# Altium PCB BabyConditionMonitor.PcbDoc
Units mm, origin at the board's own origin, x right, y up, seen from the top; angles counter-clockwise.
Board outline 40.15 x 20.15 mm, 2 copper layers (Top Layer, Bottom Layer), stack 0.791 mm thick; 52 components, 44 nets, 238 pads, 64 vias.
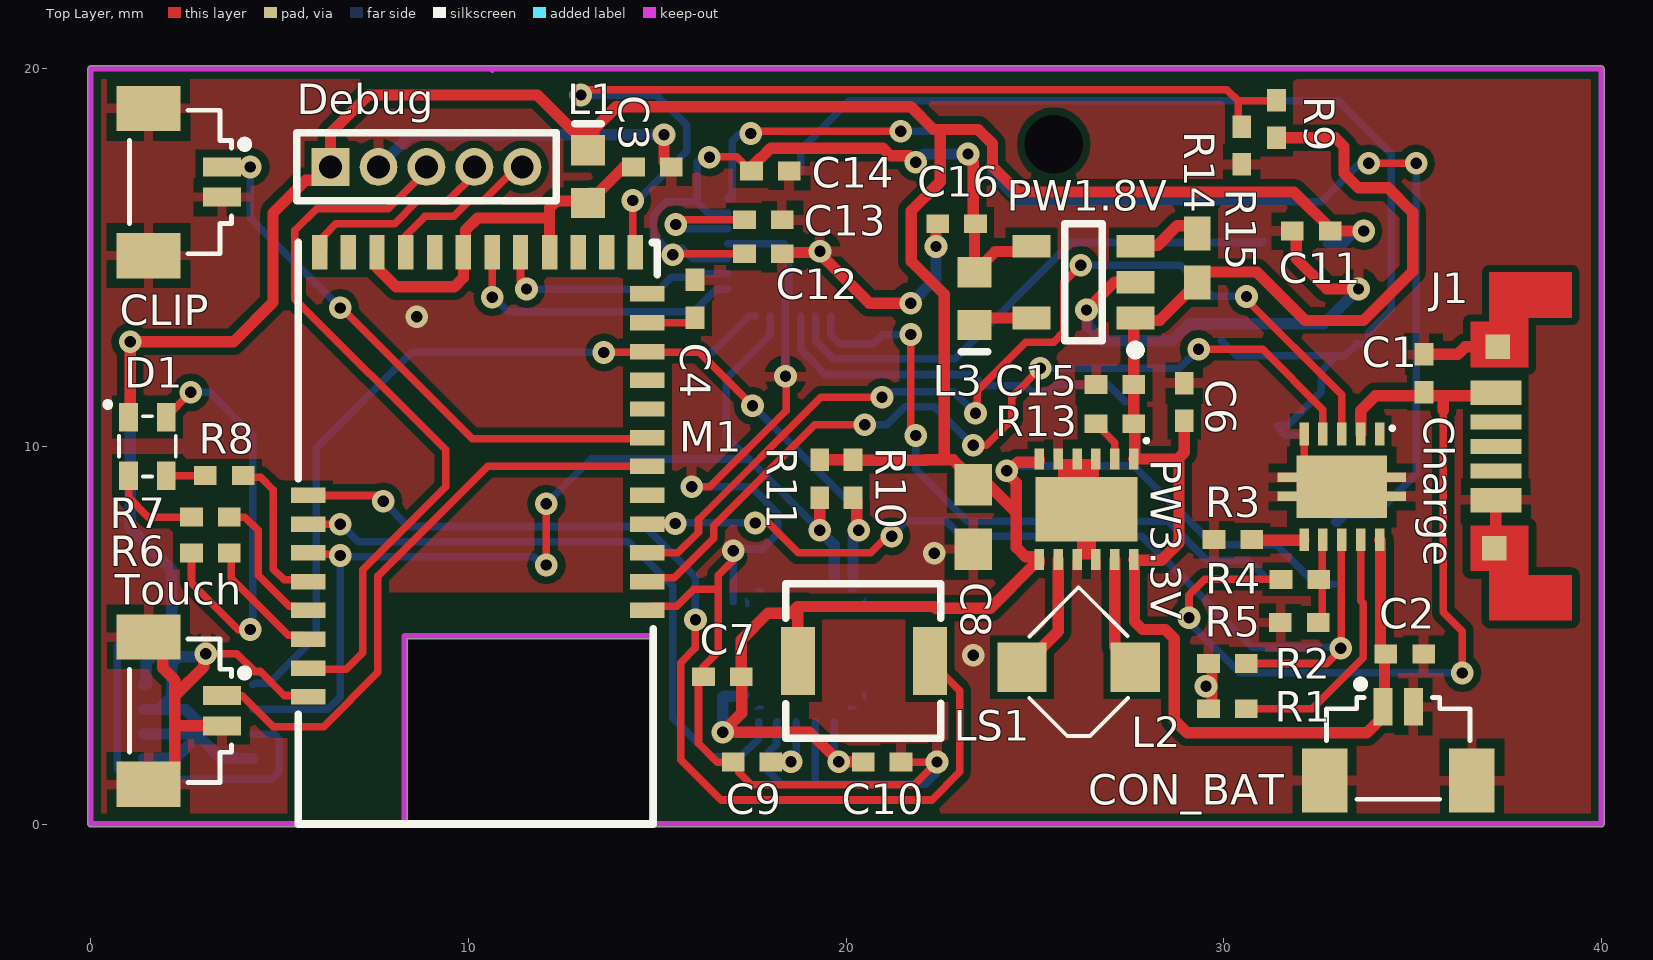
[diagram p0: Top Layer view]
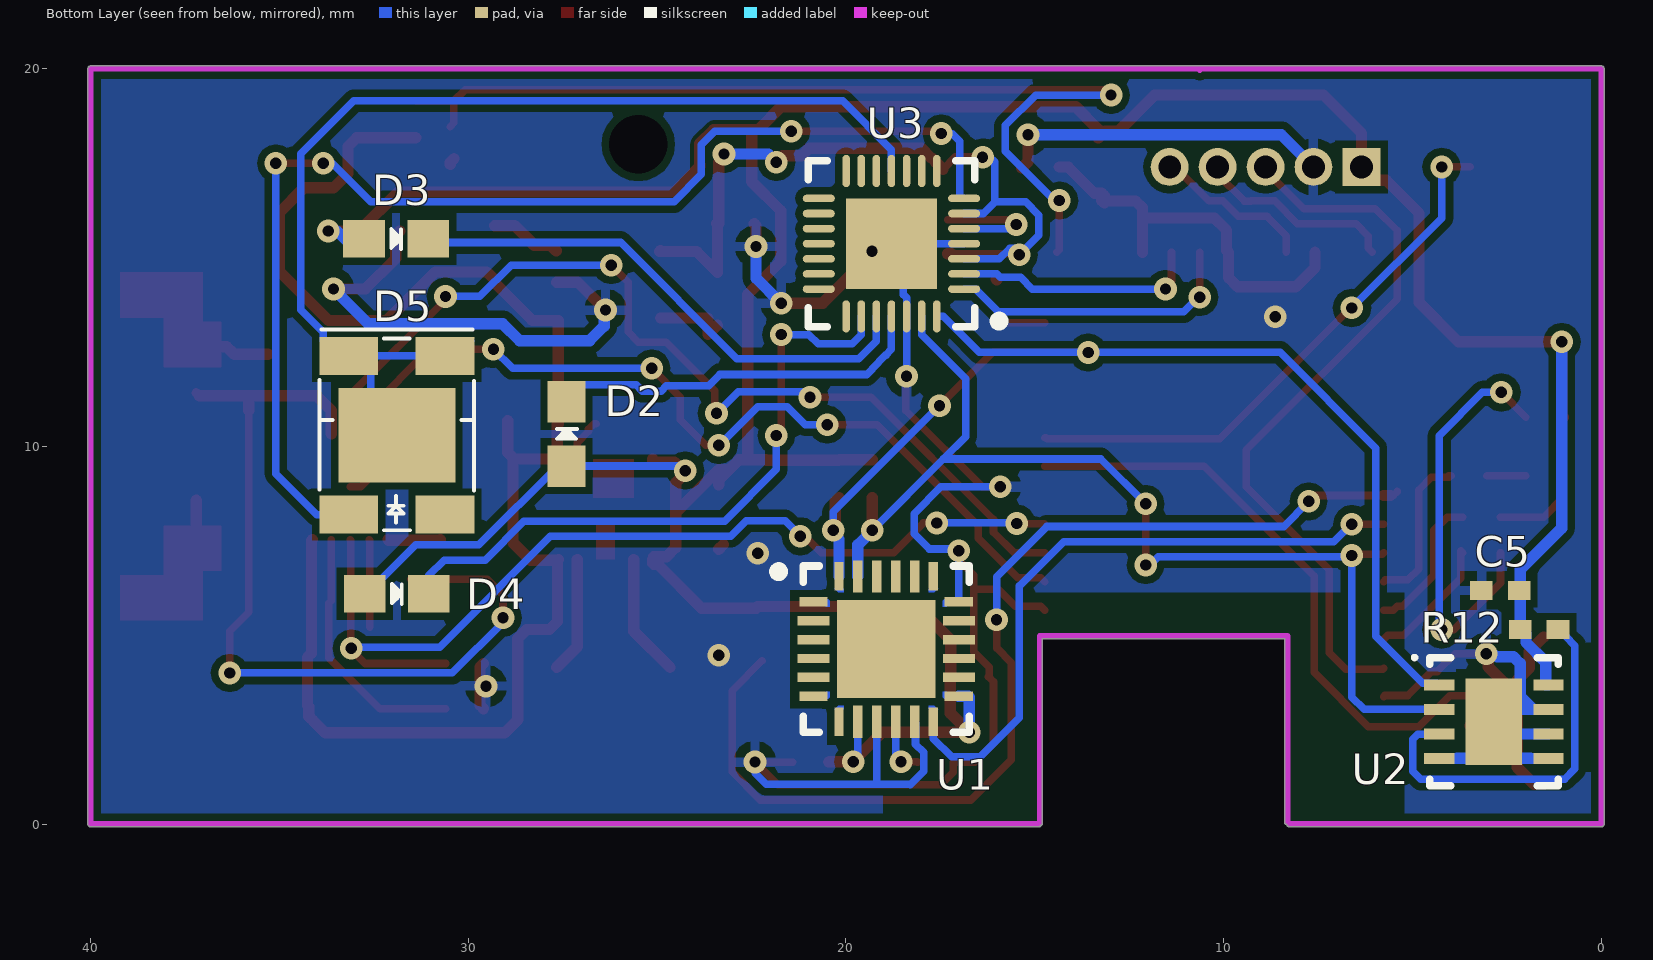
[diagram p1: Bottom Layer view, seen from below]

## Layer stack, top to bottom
Top Solder: solder mask 0.0102, Solder Resist, Dk 3.5
Top Layer: signal copper 0.0356
Dielectric 1: dielectric 0.72, FR-4, Dk 4.8
Bottom Layer: signal copper 0.0356
Bottom Solder: solder mask 0.0102, Solder Resist, Dk 3.5

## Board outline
0,-0.075 8.255,-0.075 ccw(c8.255,0) 8.328,-0.018 ccw(c8.31,0.055) 8.385,0.055 8.385,4.905 14.798,4.905 14.798,0.027 ccw(c14.873,0.027) 14.835,-0.038 ccw(c14.9,0) 14.9,-0.075 40,-0.075 ccw(c40,0) 40.075,0 40.075,20 ccw(c40,20) 40,20.075 0,20.075 ccw(c0,20) -0.075,20 -0.075,0 ccw(c0,0)

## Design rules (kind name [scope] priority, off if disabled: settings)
Clearance [All] p1: gap=0.2 ignorepadtopadclearanceinfootprint=FALSE
PasteMaskExpansion [All] p1: expansion=-0.05
PolygonConnect [All] p1: connectstyle=Relief reliefconductorwidth=0.254 reliefentries=4 polygonreliefangle="90 Angle" airgapwidth=0.254
RoomDefinition BabyConditionMonitor [InComponentClass('BabyConditionMonitor')] p1: confinementstyle=ConfineOut formatcopy=TRUE lockcomponents=FALSE outline -17.907,-42.545 192.024,-42.545 192.024,-23.622 -17.907,-23.622
RoutingVias [All] p1: holewidth=0.711 width=1.27 viastyle="Through Hole" minholewidth=0.3 minwidth=0.3 maxholewidth=0.711 maxwidth=1.27
SolderMaskExpansion [All] p1: expansion=0.102
Width [All] p1: maxlimit=0.3 minlimit=0.2 preferedwidth=0.254
29 further rules are at their usual default settings.

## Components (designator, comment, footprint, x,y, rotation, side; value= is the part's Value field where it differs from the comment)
C1 "Cap" "1005[0402] High Density" 35.306,11.938 r90 top value=1uF
C2 "Cap" "1005[0402] High Density" 34.798,4.5 r0 top value=1uF
C3 "Cap" "1005[0402] High Density" 14.873,17.399 r180 top value=1uF
C4 "Cap" "1005[0402] High Density" 16.006,13.911 r270 top value=1uF
C5 "Cap" "1005[0402] High Density" 2.675,6.183 r180 bottom value=0.1uF
C6 "Cap" "1005[0402] High Density" 28.956,11.176 r270 top value=10uF
C7 "Cap" "1005[0402] High Density" 16.726,3.9 r0 top value=0.1uF
C8 "Cap" 1608[0603] 23.368,8.128 r270 top value=22uF
C9 "Cap" "1005[0402] High Density" 17.51,1.64 r0 top value=0.47uF
C10 "Cap" "1005[0402] High Density" 20.955,1.64 r180 top value=0.01uF
C11 "Cap" "1005[0402] High Density" 32.321,15.702 r0 top value=1uF
C12 "Cap" "1005[0402] High Density" 17.81,15.1 r180 top value=0.1uF
C13 "Cap" "1005[0402] High Density" 17.81,16.002 r180 top value=1uF
C14 "Cap" "1005[0402] High Density" 17.996,17.292 r180 top value=0.1uF
C15 "Cap" "1005[0402] High Density" 27.119,11.638 r0 top value=4.7uF
C16 "Cap" "1005[0402] High Density" 22.929,15.896 r0 top value=10uF
Charge "USB Charger" BQ24020 33.131,8.93 r270 top
CLIP "SM02B-SURS-TF" SM02B-SURS-TF 2.5,17 r270 top locked
CON_BAT "SM02B-SURS-TF" SM02B-SURS-TF 34.625,2.128 r0 top
D1 "FullColorLED" "fullColorLED SMT" 1.5,10 r90 top locked
D2 "LED" "1608[0603] -LED" 27.4,10.33 r90 bottom
D3 "LED" "1608[0603] -LED" 31.914,15.5 r180 bottom
D4 "LED" "1608[0603] -LED" 31.894,6.1 r180 bottom
D5 "VEMD5010X01" "OPT Sensor VEMD5010X01" 31.894,10.295 r180 bottom locked
Debug "Header 5" MHDR1X5 6.35,17.4 r0 top
J1 "USB 2.0 CON" "MicroUSB WaterProof" 37.211,10 r270 top locked
L1 "Inductor" INDC1608L 13.163,17.145 r270 top value=300Ohm100MHz
L2 "PowerInductor" Powerinductor 26.162,4.15 r225 top value=2.2uH
L3 "Inductor" INDC1608L 23.404,13.911 r90 top value=2.2uH
LS1 "Buzzer" ST-0402T 18.725,4.318 r0 top
M1 "CYBLE-224110-00" CYBLE-224110-00 5.5,0 r180 top locked
PW1.8V "LM3671" "LM3671 SOT" 26.289,14.351 r180 top locked
PW3.3V "Buck Boost Converter" RP604x 26.369,8.336 r270 top
R1 "Res3" "1005[0402] High Density" 30.098,3.053 r0 top value=10K
R2 "Res3" "1005[0402] High Density" 30.099,4.25 r0 top value=10K
R3 "Res3" "1005[0402] High Density" 30.244,7.53 r0 top value=10K
R4 "Res3" "1005[0402] High Density" 32.021,6.477 r180 top value=10K(DNI)
R5 "Res3" "1005[0402] High Density" 32.004,5.334 r0 top value=10K
R6 "Res3" "1005[0402] High Density" 3.167,7.18 r0 top value=330
R7 "Res3" "1005[0402] High Density" 3.167,8.128 r0 top value=330
R8 "Res3" "1005[0402] High Density" 3.536,9.225 r0 top value=330
R9 "Res3" "1005[0402] High Density" 31.397,18.669 r270 top value=100K
R10 "Res3" "1005[0402] High Density" 20.185,9.144 r270 top value=4.7K
R11 "Res3" "1005[0402] High Density" 19.304,9.144 r270 top value=4.7K
R12 "Res Semi" "1005[0402] High Density" 1.644,5.15 r180 bottom value=4.7K
R13 "Res3" "1005[0402] High Density" 27.119,10.6 r0 top value=100K
R14 "" 1005[0402] 29.306,14.986 r270 top value=10K
R15 "Res3" "1005[0402] High Density" 30.48,17.967 r90 top value=100K
Touch "SM02B-SURS-TF" SM02B-SURS-TF 2.5,3 r270 top locked
U1 "Accel Gyro Sensor" MPU-6050 18.935,4.633 r180 bottom locked
U2 "Body Temperature Sensor" MAX30205 2.842,2.708 r180 bottom
U3 "HRM AFE" ADPD1080 18.796,15.367 r0 bottom locked

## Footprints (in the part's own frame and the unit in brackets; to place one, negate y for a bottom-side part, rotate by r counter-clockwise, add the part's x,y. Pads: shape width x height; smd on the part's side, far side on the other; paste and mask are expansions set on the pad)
1005[0402] [mm] "Chip Resistor; Body 1.1 x 0.5 mm (LxW typ)"
  rect 0.9x0.7 smd: 1(-0.65,0) 2(0.65,0)
  body extent -0.64,-0.24 0.64,0.26, height 0.3
"1005[0402] High Density" [mm] "Chip Body 1.0x0.5mm, IPC High Density"
  rect 0.6x0.5 smd: 1(-0.5,0) 2(0.5,0)
  body extent -0.68,-0.25 0.6,0.25, height 0.3
1608[0603] [mm] "Chip Capacitor; Body 1.6 x 0.8 mm (LxW typ)"
  rect 1.1x1 smd: 1(-0.85,0) 2(0.85,0)
"1608[0603] -LED" [mm] "Chip Capacitor; Body 1.6 x 0.8 mm (LxW typ)"
  rect 1.1x1 smd: 1(-0.85,0) 2(0.85,0)
  silkscreen extent -0.13,-0.28 0.13,0.25, body extent -1.08,-0.42 1.05,0.41, height 0.6
ADPD1080 [mm] "QFN, 28-Leads, Body 4.00x4.00mm, Pitch 0.40mm, Thermal Pad 2.60x2.60mm, IPC Medium Density"
  oval 0.85x0.2 smd: 1(-1.925,1.2) 2(-1.925,0.8) 3(-1.925,0.4) 4(-1.925,0) 5(-1.925,-0.4) 6(-1.925,-0.8) 7(-1.925,-1.2) 15(1.925,-1.2) 16(1.925,-0.8) 17(1.925,-0.4) 18(1.925,0) 19(1.925,0.4) 20(1.925,0.8) 21(1.925,1.2)
  oval 0.2x0.85 smd: 8(-1.2,-1.925) 9(-0.8,-1.925) 10(-0.4,-1.925) 11(0,-1.925) 12(0.4,-1.925) 13(0.8,-1.925) 14(1.2,-1.925) 22(1.2,1.925) 23(0.8,1.925) 24(0.4,1.925) 25(0,1.925) 26(-0.4,1.925) 27(-0.8,1.925) 28(-1.2,1.925)
  rect 2.4x2.4 smd: 29(0,0)
  silkscreen extent -2.97,-2.2 2.2,2.2, body extent -2.07,-2.07 2.07,2.07, height 0.8
BQ24020 [mm] "BATTERY CHARGER"
  rect 0.6x0.25 smd: 1(-1.4,1) 2(-1.4,0.5) 3(-1.4,0) 4(-1.4,-0.5) 5(-1.4,-1) 6(1.4,-1) 7(1.4,-0.5) 8(1.4,0) 9(1.4,0.5) 10(1.4,1)
  rect 0.25x1 smd: 11(-0.25,1.2) 11(-0.25,-1.2) 11(0.25,1.2) 11(0.25,-1.2)
  rect 1.65x2.4 smd: 11(0,0)
  silkscreen extent -1.6,1.29 -1.5,1.39, body extent -1.05,-1.05 1.05,1.05, height 1
CYBLE-224110-00 [mm]
  rect 0.91x0.41 smd: 1(-0.26,-3.37) 2(-0.26,-4.13) 3(-0.26,-4.89) 4(-0.26,-5.66) 5(-0.26,-6.42) 6(-0.26,-7.18) 7(-0.26,-7.94) 8(-0.26,-8.7) 21(-9.24,-14.04) 22(-9.24,-13.28) 23(-9.24,-12.51) 24(-9.24,-11.75) 25(-9.24,-10.99) 26(-9.24,-10.23) 27(-9.24,-9.47) 28(-9.24,-8.7) 29(-9.24,-7.94) 30(-9.24,-7.18) 31(-9.24,-6.42) 32(-9.24,-5.66)
  rect 0.41x0.91 smd: 9(-0.56,-15.14) 10(-1.32,-15.14) 11(-2.08,-15.14) 12(-2.84,-15.14) 13(-3.61,-15.14) 14(-4.37,-15.14) 15(-5.13,-15.14) 16(-5.88,-15.14) 17(-6.65,-15.14) 18(-7.41,-15.14) 19(-8.17,-15.14) 20(-8.92,-15.14)
  silkscreen extent -9.5,-15.4 0,0, body extent -9.5,-15.41 0,-0.02, height 3.75
"fullColorLED SMT" [mm] "OSTB0603C1C-A"
  rect 0.75x0.5 smd: 1(0.775,0.5) 2(0.775,-0.5) 3(-0.775,0.5) 4(-0.775,-0.5)
  silkscreen extent -0.8,-0.75 1.13,1.07, body extent -0.74,-0.62 0.74,0.67, height 0.6
INDC1608L [mm] "Chip Inductor, Body 1.6x0.8mm, IPC High Density"
  rect 0.8x0.9 smd: 1(-0.7,0) 2(0.7,0)
  silkscreen extent -1.4,-0.35 -1.4,0.35, body extent -0.87,-0.48 0.87,0.48, height 0.55
"LM3671 SOT" [mm] "SOT23 LM3671 StepDown DCDC"
  rect 1x0.6 smd: 1(-1.375,0.95) 2(-1.375,0) 3(-1.375,-0.95) 4(1.375,-0.95) 5(1.375,0.95)
  silkscreen extent -1.5,-1.55 0.5,1.92
MAX30205 [mm] "Body Temperature Sensor"
  rect 0.8x0.3 smd mask+0: 1(-1.445,0.975) 2(-1.445,0.325) 3(-1.445,-0.325) 4(-1.445,-0.975) 5(1.445,-0.975) 6(1.445,-0.325) 7(1.445,0.325) 8(1.445,0.975)
  rect 1.5x2.3 smd: 4(0,0)
  silkscreen extent -2.15,-1.7 1.7,1.75, body extent -1.55,-1.55 1.55,1.55, height 0.8
MHDR1X5 [mm] "Connector; Header; 5 Position"
  rect 1x1 hole 0.6: 1(0,0)
  round 1 hole 0.6: 2(1.27,0) 3(2.54,0) 4(3.81,0) 5(5.08,0)
  silkscreen extent -0.9,-0.9 5.98,0.9
"MicroUSB WaterProof" [mm]
  rect 0.65x0.65 smd: 0(-2.64,0.05) 0(2.7,-0.05)
  rect 0.65x1.35 smd: 1(-1.425,0) 5(1.425,0)
  rect 0.4x1.35 smd: 2(-0.65,0) 3(0,0) 4(0.65,0)
  Top Layer region: 2,-0.69
  Top Layer region: 2.1,-0.67 3.3,-0.67 3.3,-0.17 4.61,-0.17 4.61,2.01 3.41,2.01 3.41,0.86 2.1,0.86
  Top Layer region: 2.1,-0.67 3.3,-0.67 3.3,-0.17 4.61,-0.17 4.61,2.01 3.41,2.01 3.41,0.86 2.1,0.86
  Top Layer region: -2.1,-0.67 -3.3,-0.67 -3.3,-0.17 -4.61,-0.17 -4.61,2.01 -3.41,2.01 -3.41,0.86 -2.1,0.86
  body extent -5.75,0 5.75,6.15, height 4.12
MPU-6050 [mm] "QFN, 24-Leads, Body 4.00x4.00mm, Pitch 0.50mm, Thermal Pad 2.60x2.60mm, IPC Medium Density"
  rect 0.75x0.25 smd: 1(-1.925,1.25) 6(-1.925,-1.25) 13(1.925,-1.25) 18(1.925,1.25)
  rect 0.85x0.25 smd: 2(-1.925,0.75) 3(-1.925,0.25) 4(-1.925,-0.25) 5(-1.925,-0.75) 14(1.925,-0.75) 15(1.925,-0.25) 16(1.925,0.25) 17(1.925,0.75)
  rect 0.25x0.75 smd: 7(-1.25,-1.925) 12(1.25,-1.925) 19(1.25,1.925) 24(-1.25,1.925)
  rect 0.25x0.85 smd: 8(-0.75,-1.925) 9(-0.25,-1.925) 10(0.25,-1.925) 11(0.75,-1.925) 20(0.75,1.925) 21(0.25,1.925) 22(-0.25,1.925) 23(-0.75,1.925)
  rect 2.6x2.6 smd: 25(0,0)
  Top Layer region: -1.375,1.6 -1.275,1.5 -1.125,1.5 -1.125,1.6
  Top Layer region: -1.6,1.375 -1.5,1.275 -1.5,1.125 -1.6,1.125
  Top Layer region: 1.6,1.375 1.5,1.275 1.5,1.125 1.6,1.125
  Top Layer region: 1.6,-1.125 1.5,-1.125 1.5,-1.275 1.6,-1.375
  Top Layer region: 1.375,-1.6 1.275,-1.5 1.125,-1.5 1.125,-1.6
  Top Layer region: -1.375,-1.6 -1.275,-1.5 -1.125,-1.5 -1.125,-1.6
  Top Layer region: -1.6,-1.375 -1.5,-1.275 -1.5,-1.125 -1.6,-1.125
  Top Layer region: 1.125,1.6 1.375,1.6 1.275,1.5 1.125,1.5
  silkscreen extent -2.98,-2.2 2.2,2.2, body extent -2.05,-2.05 2.05,2.05, height 0.95
"OPT Sensor VEMD5010X01" [mm]
  rect 1.55x1 smd: 1(-1.275,-2.1) 2(-1.275,2.1) 2(1.275,2.1) ""(1.275,-2.1)
  rect 3.1x2.5 smd: 2(0,0)
  silkscreen extent -2.05,-2.51 2.05,2.8, body extent -2.06,-2.51 2.03,2.76, height 2.05
Powerinductor [mm] "CDRH2D14"
  rect 1.3x1.3 smd rot 45: 1(-1.06,1.06) 2(1.06,-1.06)
  silkscreen extent -1.5,-1.5 1.5,1.5
RP604x [mm] "SON, 12-Leads, Body 3.00x2.70mm, Pitch 0.50mm, Thermal Pad 2.70x1.70mm, IPC High Density"
  rect 0.55x0.25 smd mask+0: 1(-1.33,1.25) 2(-1.33,0.75) 3(-1.33,0.25) 4(-1.33,-0.25) 5(-1.33,-0.75) 6(-1.33,-1.25) 7(1.33,-1.25) 8(1.33,-0.75) 9(1.33,-0.25) 10(1.33,0.25) 11(1.33,0.75) 12(1.33,1.25)
  rect 1.7x2.7 smd: 10(0,0)
  silkscreen extent -1.87,1.54 -1.77,1.64, body extent -1.38,-1.53 1.38,1.53, height 0.58
SM02B-SURS-TF [mm]
  rect 0.5x1 smd: 1(-0.4,0.975) 2(0.4,0.975)
  rect 1.2x1.7 smd: Pad(-1.95,-0.975) Pad(1.95,-0.975)
  silkscreen extent -1.9,-1.47 1.9,1.68
ST-0402T [mm] "Buzzer SMC"
  rect 0.9x1.8 smd: 1A(0,0) 2A(3.5,0)
  silkscreen extent -0.32,-2.05 3.79,2.05, body extent -0.32,-2.05 3.79,2.05, height 2

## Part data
C1 C2 C3 C4 C5 C6 C7 C8 C9 C10 C11 C12 C13 C14 C15 C16: "Capacitor"
Charge: library part BQ2402X, PartNo=BQ24020
D1: PartNo=OSTB0603C1C-A
D2 D3 D4: "LED SMD"
Debug: "Header, 5-Pin"
J1: library part USBConnector, "USB2.0 Connector", Manufacture=Molex, PartNo=DX4RNW5HJ3R1000
L2: Manufacture=Sumida, PartNo=CDRH2D14NP-2R2NC
L3: Manufacture=Abracon-LLC, PartNo=ASMPH-0603-2R2M-T
LS1: "Magnetic Transducer Buzzer", Supplier Part Number 1=433-1110-1-ND
M1: "BLE Module Long Range"
PW1.8V: "StepDownDCDC", Manufacture="Texas Instruments"
PW3.3V: library part RP604x, Manufacture=Ricoh, PartNo=RP604K331A
R1 R2 R3 R4 R5 R6 R7 R8 R9 R10 R11 R13 R15: "Resistor"
R12: "Semiconductor Resistor"
R14: library part Res3, "Resistor"
U1: library part MPU-6050, Manufacture="TDK InvenSense", PartNo=ICM-20689
U2: library part MAX30205, "Body Temperature Sebsor", Manufature=Maxim
U3: library part ADPD1080, Manufacturer="Analog Devices", Manufacturer Part Number=ADPD1080BCPZ, Supplier Part Number 1=ADPD1080BCPZ-ND

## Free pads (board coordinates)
  round 0.6 hole 1.55: 6(25.5,18)

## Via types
v1: diameter 0.6, hole 0.3, Top Layer to Bottom Layer, tented both sides, 64 vias

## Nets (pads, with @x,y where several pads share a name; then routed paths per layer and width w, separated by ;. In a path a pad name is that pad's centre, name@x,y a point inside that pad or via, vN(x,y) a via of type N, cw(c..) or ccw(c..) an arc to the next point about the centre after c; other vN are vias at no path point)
ACCEL_INT: M1.7 U1.12 | length 17.2
  Top Layer w0.2: M1.7 v1(6.604,7.94)
  Bottom Layer w0.2: v1(6.604,7.94) 6.625,7.94 7.087,7.478 14.237,7.478 15.413,6.302 15.413,2.816 16.451,1.778 17.204,1.778 17.685,2.259 U1.12
ACCEL_SCL: M1.6 R11.2 U1.23 U2.2 U3.27 | length 29.5
  Top Layer w0.2: M1.6 5.794,7.146 6.57,7.146 v1(6.604,7.112) ; v1(12.065,6.858) v1(12.065,8.478)
  Top Layer w0.3: v1(19.304,7.781) R11.2
  Bottom Layer w0.2: U2.2 6.28,3.033 6.604,3.357 v1(6.604,7.112) 6.638,7.078 11.737,7.078 11.957,6.858 v1(12.065,6.858) ; v1(12.065,8.478) 13.253,9.666 17.419,9.666 ; U3.27 17.996,12.951 16.83,11.785 16.83,10.255 17.419,9.666 ; v1(19.304,7.781) 17.419,9.666
  Bottom Layer w0.3: v1(19.304,7.781) 19.304,7.772 19.685,7.391 U1.23
ACCEL_SDA: M1.23 R10.2 U1.24 U2.1 U3.28 | length 31.5
  Top Layer w0.2: v1(13.589,12.488) 16.111,12.488 v1(17.526,11.073)
  Top Layer w0.3: R10.2 20.285,8.544 20.285,7.832 v1(20.336,7.781)
  Bottom Layer w0.2: U2.1 4.337,3.733 4.726,3.733 5.969,4.976 5.969,9.953 8.504,12.488 v1(13.589,12.488) 16.467,12.488 17.421,13.442 U3.28 ; v1(17.526,11.073) 20.336,8.263 v1(20.336,7.781)
  Bottom Layer w0.3: U1.24 20.185,7.549 20.336,7.7 v1(20.336,7.781)
EN_1.8V: PW1.8V.3 R14.1 | length 1.9
  Top Layer w0.3: PW1.8V.3@27.671,15.18 27.818,15.327 28.256,15.327 28.774,15.845 R14.1@29.306,15.845
NetC3_2: C3.2 L1.2 M1.11 M1.14 M1.17 | length 10.9
  Top Layer w0.3: M1.11 7.58,14.732 8.088,14.224 9.625,14.224 9.87,14.469 M1.14 9.925,15.195 9.925,15.728 10.247,16.05 12.071,16.05 12.15,16.129 ; M1.17 12.15,16.129 ; L1.2 13.226,16.508 L1.2@13.226,16.7 ; C3.2@14.359,17.399 14.117,17.399 13.415,16.697 13.413,16.7 L1.2@13.226,16.7 ; 12.15,16.129 12.15,16.32 12.33,16.5 13.113,16.5 13.163,16.55 13.163,16.637 L1.2@13.226,16.7
NetC4_2: C4.2 M1.22 | length 1.3
  Top Layer w0.2: M1.22 15.875,13.28 C4.2
NetC9_2: C9.2 U1.10 | length 1.6
  Top Layer w0.2: C9.2@18.107,1.64 18.112,1.646 18.537,1.646 v1(18.542,1.651)
  Bottom Layer w0.2: v1(18.542,1.651) 18.659,1.768 18.685,1.768 U1.10
NetC13_2: C13.2 U3.5 | length 3.2
  Top Layer w0.2: v1@15.494,16.002 C13.2
  Bottom Layer w0.2: v1(15.494,15.875) 15.602,15.875 15.71,15.767 U3.5
NetCharge_3: Charge.3 M1.30 | length 25.8
  Top Layer w0.2: M1.30 15.545,7.18 16.094,7.729 16.094,8.064 19.333,11.303 v1(20.955,11.303) ; v1(23.429,10.876) 23.477,10.924 23.477,11.476 24.762,12.761 25.498,12.761 25.769,13.032 25.769,14.35 v1(26.219,14.8) ; v1@30.566,13.929 33.131,11.364 Charge.3
  Bottom Layer w0.2: v1(20.955,11.303) 20.986,11.303 21.133,11.45 22.855,11.45 v1(23.429,10.876) ; v1(26.219,14.8) 28.866,14.8 29.696,13.97 v1(30.607,13.97)
NetCharge_4: Charge.4 M1.31 | length 23.2
  Top Layer w0.2: M1.31 14.845,6.525 15.455,6.525 16.494,7.564 16.494,7.898 19.172,10.576 v1(20.496,10.576) ; v1(23.368,10.033) 23.713,10.033 24.384,10.704 24.384,11.303 v1(25.146,12.065) ; v1(29.337,12.573) 31.033,12.573 32.631,10.975 Charge.4
  Bottom Layer w0.2: v1(20.496,10.576) 21.07,10.576 21.073,10.573 21.55,11.05 22.336,11.05 23.11,10.276 v1(23.368,10.033) v1@23.434,10.033 ; v1(25.146,12.065) 28.829,12.065 v1(29.337,12.573)
NetCharge_6: Charge.6 R3.2 | length 1.4
  Top Layer w0.3: R3.2 30.761,7.513 32.114,7.513 Charge.6
NetCharge_7: Charge.7 R4.1 R5.2 | length 2.3
  Top Layer w0.2: R5.2@32.614,5.211 32.614,5.45 32.614,6.336 32.614,7.513 Charge.7
NetCharge_8: Charge.8 M1.29 R2.2 | length 26.2
  Top Layer w0.2: M1.29 14.749,7.949 15.466,7.949 v1(15.475,7.959) ; v1(17.596,7.973) 17.947,7.973 18.74,7.18 20.658,7.18 21.098,7.62 v1(21.209,7.62) v1@21.409,7.62 ; R2.2 32.729,4.25 33.098,4.619 v1(33.098,4.652) 33.121,4.675 33.121,7.52 Charge.8
  Bottom Layer w0.2: v1(15.475,7.959) 15.489,7.973 v1(17.596,7.973) ; v1(21.209,7.62) 21.615,8.026 22.642,8.026 23.048,7.62 27.829,7.62 30.764,4.685 33.098,4.685 v1(33.098,4.652)
NetCharge_9: Charge.9 R1.2 | length 6.8
  Top Layer w0.2: R1.2 30.603,3.048 32.343,3.048 33.698,4.403 33.698,5.846 33.631,5.913 Charge.9
NetCLIP_1: CLIP.1 M1.26 | length 15
  Top Layer w0.2: CLIP.1 v1(4.225,17.399) ; v1(6.604,13.667) 6.637,13.667 10.101,10.203 14.673,10.203 14.7,10.23 M1.26
  Bottom Layer w0.2: v1(4.225,17.399) 4.225,16.046 v1(6.604,13.667)
NetD1_2: D1.2 R6.1 | length 11.1
  Top Layer w0.2: D1.2 1.998,10.777 1.994,10.777 v1(2.647,11.43) ; R6.1 2.667,6.386 3.903,5.15 v1(4.225,5.15)
  Bottom Layer w0.2: v1(2.647,11.43) 3.146,11.43 4.29,10.286 4.29,5.215 v1(4.225,5.15)
NetD1_3: D1.3 R7.1 | length 2.5
  Top Layer w0.2: D1.3 1,8.652 1.524,8.128 2.487,8.128 R7.1
NetD1_4: D1.4 R8.1 | length 1
  Top Layer w0.2: D1.4 R8.1
NetD2_2: D2.2 U3.25 | length 10.2
  Bottom Layer w0.2: U3.25 18.796,12.574 18.95,12.42 18.941,12.411 18.959,12.411 19.31,12.06 19.31,12.042 19.449,11.903 23.338,11.903 23.64,11.601 24.761,11.601 24.897,11.465 25.395,11.465 25.56,11.63 26.95,11.63 D2.2
NetD3_2: D3.2 U3.24 | length 14
  Bottom Layer w0.2: U3.24 19.196,12.786 19.665,12.317 22.887,12.317 25.97,15.4 31.014,15.4 D3.2@31.064,15.45
NetD4_2: D4.2 U3.23 | length 17.3
  Top Layer w0.2: v1(21.717,12.961) 21.717,10.414 v1(21.844,10.287)
  Bottom Layer w0.2: U3.23 19.596,12.951 19.83,12.717 20.737,12.717 20.981,12.961 v1(21.717,12.961) ; D4.2@31.044,6.59 30.644,6.99 29.559,6.99 28.529,8.02 23.214,8.02 21.844,9.39 v1(21.844,10.287) ; v1(21.844,10.287) 21.844,10.448 21.683,10.287 v1(21.844,10.287)
NetD5_1: D5.1 U3.7 | length 32.5
  Top Layer w0.2: v1(17.476,18.285) 17.417,18.344 v1(21.448,18.344) ; v1(33.84,17.495) v1(35.098,17.495)
  Bottom Layer w0.2: U3.7 16.983,16.567 16.983,18.083 17.185,18.285 v1(17.476,18.285) ; v1(21.448,18.344) 23.477,18.344 23.829,17.992 23.829,17.206 24.552,16.483 32.589,16.483 33.6,17.495 v1(33.84,17.495) ; D5.1 34.021,8.195 35.098,9.272 v1(35.098,17.495)
  Bottom Layer w0.3: D5.1@32.994,8.02 D5.1
NetD5_2: D5.2 U3.11 | length 30
  Bottom Layer w0.2: U3.11 18.796,17.86 20.086,19.15 33.034,19.15 34.44,17.744 34.44,13.623 33.84,13.023 33.84,12.795 33.756,12.711 33.528,12.711 33.212,12.395 33.169,12.395 D5.2@32.991,12.395 ; D5.2@29.944,12.795 30.344,12.395 30.619,12.395 D5.2@32.991,12.395 ; D5.2@31.894,10.295 31.65,10.295 31.404,10.541 31.687,10.541 32.591,11.445 32.591,11.995 D5.2@32.991,12.395
NetL2_1: L2.1 PW3.3V.11 | length 3.1
  Top Layer w0.3: PW3.3V.11 27.119,4.692 L2.1
NetL2_2: L2.2 PW3.3V.8 | length 3.3
  Top Layer w0.3: L2.2 25.619,5.106 PW3.3V.8
NetL3_1: L3.1 PW1.8V.5 | length 2.1
  Top Layer w0.3: L3.1 23.654,12.961 23.654,13.401 PW1.8V.5
NetLS1_2: LS1.2A M1.8 | length 27.9
  Top Layer w0.2: M1.8@5.405,8.805 5.51,8.7 M1.8@5.588,8.7 ; M1.8 7.591,8.7 v1(7.747,8.544) ; v1(16.013,5.413) 16.013,4.661 15.626,4.274 15.626,1.7 16.691,0.635 22.266,0.635 23.009,1.378 23.009,3.534 LS1.2A
  Top Layer w0.3: M1.8@5.588,8.7 M1.8
  Bottom Layer w0.2: v1(7.747,8.544) 8.413,7.878 14.686,7.878 16.013,6.551 v1(16.013,5.413)
NetM1_3: M1.3 R6.2 | length 3.5
  Top Layer w0.2: R6.2 3.667,7.189 3.717,7.239 3.717,6.507 5.229,4.995 5.655,4.995 M1.3
NetM1_4: M1.4 R7.2 | length 3.8
  Top Layer w0.2: R7.2 4.083,8.128 4.436,7.775 4.436,6.587 5.258,5.765 5.405,5.765 5.51,5.66 M1.4
NetM1_5: M1.5 R8.2 | length 4.2
  Top Layer w0.2: R8.2 3.976,9.225 4.021,9.18 4.501,9.18 4.836,8.845 4.836,6.753 5.122,6.466 5.714,6.466 M1.5
NetM1_15: M1.15 U3.1 | length 7.8
  Top Layer w0.2: M1.15 10.634,15.136 v1(10.634,13.951)
  Bottom Layer w0.2: v1(10.634,13.951) 10.667,13.951 11.051,13.567 15.962,13.567 16.546,14.151 16.546,14.167 U3.1
NetM1_16: M1.16 U3.2 | length 6.5
  Top Layer w0.2: M1.16 11.38,14.385 11.54,14.225 v1(11.54,14.167)
  Bottom Layer w0.2: v1(11.54,14.167) 15.062,14.167 15.37,14.475 15.912,14.475 16.004,14.567 U3.2
NetM1_20: M1.20 R9.1 R15.2 | length 26.5
  Top Layer w0.2: v1(12.98,19.304) 13.12,19.444 30.088,19.444 30.382,19.15 ; v1(14.351,16.51) 14.351,15.209 M1.20 ; R15.2 30.382,18.565 30.382,19.15 ; R9.1@31.397,19.15 30.382,19.15
  Bottom Layer w0.2: v1(12.98,19.304) 14.973,19.304 15.778,18.499 15.778,17.818 14.471,16.51 v1(14.351,16.51)
NetM1_27: M1.27 Touch.1 | length 16
  Top Layer w0.2: Touch.1 4.007,3.4 4.827,2.58 6.169,2.58 7.604,4.015 7.604,6.567 10.507,9.47 M1.27
NetR12_2: R12.2 U2.3 | length 10
  Bottom Layer w0.2: R12.2@1.124,5.15 1.094,5.15 0.944,5 0.944,4.97 0.697,4.723 0.697,1.459 0.973,1.183 4.778,1.183 4.992,1.397 4.992,2.241 4.856,2.377 4.293,2.377 U2.3
  Bottom Layer w0.3: R12.2@1.124,5.15 R12.2
PW_3.3V_CONTROL: PW3.3V.2 R13.1 | length 1.2
  Top Layer w0.2: R13.1 26.669,10.6 26.819,10.45 26.819,10.4 27.119,10.1 PW3.3V.2
SWDCK: Debug.4 M1.9 | length 5.4
  Top Layer w0.2: M1.9 6.165,15.245 6.165,15.569 6.491,15.895 8.046,15.895 8.651,16.5 9.271,16.5 9.281,16.49 9.446,16.49 10.195,17.239 10.16,17.274 Debug.4
SWDIO: Debug.5 M1.12 | length 4.3
  Top Layer w0.2: M1.12 8.34,15.579 8.851,16.09 9.612,16.09 10.022,16.5 10.391,16.5 11.291,17.4 Debug.5
VCC_1.8V: C12.2 C14.2 C16.2 L3.2 PW1.8V.4 U3.3 U3.6 | length 20.9
  Top Layer w0.2: v1(15.413,15.075) 15.438,15.1 C12.2@17.21,15.1 ; v1@16.383,17.665 17.105,17.665 C14.2@17.43,17.34
  Top Layer w0.3: C12.2@17.21,15.1 C12.2 ; C14.2@17.43,17.34 17.616,17.526 17.63,17.526 17.63,17.54 17.725,17.635 17.745,17.635 18.004,17.894 20.979,17.894 21.179,17.694 21.676,17.694 v1(21.844,17.526) ; v1(23.229,17.744) 23.229,17.662 23.369,17.522 23.369,15.896 C16.2 23.404,15.871 L3.2 23.956,15.163 24.938,15.163 PW1.8V.4@24.921,15.18
  Bottom Layer w0.2: v1(16.383,17.653) 16.306,17.576 16.103,17.576 16.062,17.536 16.062,16.467 ; U3.3 15.938,14.967 15.665,15.24 15.413,15.24 15.379,15.206 15.282,15.206 14.894,15.594 14.894,16.124 15.245,16.475 16.054,16.475 16.062,16.467 ; U3.6 16.362,16.167 16.062,16.467
  Bottom Layer w0.3: v1(21.844,17.526) 22.062,17.744 v1(23.229,17.744)
VCC_BAT: C2.1 C6.2 C15.2 Charge.10 CON_BAT.1 PW1.8V.1 PW3.3V.1 PW3.3V.12 R9.2 R13.2 R14.2 | length 40.7
  Top Layer w0.3: PW3.3V.12 PW3.3V.12@27.64,6.985 ; C6.2 28.956,9.838 28.818,9.7 ; R9.2 32.962,18.169 33.19,17.941 33.19,17.226 33.571,16.845 34.359,16.845 35.006,16.198 35.006,14.635 33.706,13.335 32.161,13.335 30.876,14.62 29.506,14.62 29.306,14.42 R14.2 28.305,13.335 27.619,13.335 C15.2 R13.2 27.646,10.573 27.646,9.881 27.644,9.879 27.644,9.691 PW3.3V.1 28.784,9.666 28.818,9.7 ; Charge.10 34.156,7.505 34.156,4.525 34.262,4.419 34.262,3.14 CON_BAT.1 34.225,2.847 34.181,2.803 34.175,2.803 34.125,2.753 34.125,2.747 33.791,2.413 29.037,2.413 28.694,2.756 28.694,4.912 28.456,5.15 27.852,5.15 27.64,5.362 PW3.3V.12@27.64,6.985 ; PW3.3V.12@27.64,6.985 28.356,6.985 28.818,7.447 28.818,9.7
VIN_5V: C1.1 Charge.2 J1.1 R4.2 | length 23.1
  Top Layer w0.2: v1(29.083,5.461) 29.083,6.055 29.505,6.477 R4.2 ; 35.814,10.953 35.814,5.614 36.322,5.106 v1(36.322,4)
  Top Layer w0.254: J1.1@37.125,11.339 J1.1
  Top Layer w0.3: Charge.2 33.631,10.951 34.019,11.339 35.814,11.339 ; 35.814,10.953 35.814,11.339 ; J1.1@37.125,11.339 35.814,11.339
  Bottom Layer w0.2: v1(29.083,5.461) 29.083,5.341 30.424,4 v1(36.322,4)
WGND: C1.2 C2.2 C3.1 C4.1 C5.1 C6.1 C7.1 C8.2 C9.1 C10.1 C11.1 C12.1 C13.1 C14.1 C15.1 C16.1 Charge.5 Charge.11 CLIP.2 CLIP.Pad CON_BAT.2 CON_BAT.Pad Debug.2 J1.0 J1.5 M1.1 M1.32 PW1.8V.2 PW3.3V.3 PW3.3V.4 PW3.3V.5 PW3.3V.9 PW3.3V.10 R1.1 R2.1 R3.1 R5.1 R15.1 Touch.2 Touch.Pad U1.9 U1.11 U1.18 U2.4 U2.5 U2.6 U2.7 U3.4 U3.26 U3.29 | length 94.2
  Top Layer w0.2: v1(3.048,4.508) 3.868,4.508 4.337,4.039 4.486,4.039 5.122,3.403 5.727,3.403 M1.1 ; M1.32 14.845,5.765 15.516,5.765 15.971,6.219 16.613,6.219 ; v1(15.912,8.93) 16.395,8.93 18.415,10.95 18.415,12.002 18.269,11.856 v1(18.396,11.856) ; v1@17.087,7.06 16.613,6.585 16.613,6.219 ; C10.1 21.405,1.64 v1(22.409,1.64) 21.811,1.042 17.486,1.042 17.157,1.371 17.157,1.64 16.589,1.64 16.094,2.135 16.094,3.768 C7.1 16.206,3.92 16.206,4.15 16.613,4.557 16.613,6.219 ; Charge.5 32.131,9.655 32.856,8.93 Charge.11@33.131,8.93
  Top Layer w0.3: Touch.Pad@1.525,1.05 1.775,1.05 2.225,1.5 2.225,2.708 ; Touch.Pad@1.525,4.95 1.905,4.57 1.905,4.13 2.225,3.81 2.225,3.395 ; v1(3.048,4.508) 2.991,4.451 2.991,4.161 2.225,3.395 ; Touch.2 2.333,2.6 2.225,2.708 ; v1(15.178,18.25) 15.178,17.538 C3.1@15.345,17.371 ; C4.1 C4.1@16.026,14.431 ; C12.1@18.265,15.055 C12.1 18.344,15.133 19.276,15.133 20.618,13.792 v1(21.717,13.792) ; v1(22.381,15.292) 22.381,15.849 C16.1 ; C8.2@23.242,7.404 C8.2 ; v1(26.369,13.611) 27.109,14.351 PW1.8V.2 ; v1(29.532,3.65) 29.534,3.652 29.694,3.652 29.694,4.155 R2.1 ; R1.1 29.694,3.149 v1@29.694,3.65 ; R15.1@30.38,17.617 30.48,17.517 R15.1 ; C11.1 31.921,15.602 31.921,14.98 32.734,14.167 v1(33.571,14.167) ; C1.2 36.2,12.438 36.402,12.64 J1.0@37.261,12.64 ; J1.0@37.161,7.3 37.211,7.35 J1.5 ; 2.225,2.708 2.225,3.395
  Bottom Layer w0.2: v1(15.912,8.93) 17.488,8.93 18.196,8.221 18.196,7.689 17.79,7.283 17.062,7.283 v1(17.018,7.239) 17.018,7.096 17.01,7.088 U1.18 ; U3.4 U3.29@18.36,15.367 ; U1.11 18.16,2.683 18.16,2.118 17.942,1.9 17.942,1.402 18.302,1.042 18.311,1.051 19.185,1.051 ; v1(18.396,11.856) U3.26 18.396,13.933 18.486,14.023 18.486,15.057 U3.29@18.594,15.165 ; U1.9 19.185,1.09 19.224,1.051 22.117,1.051 22.409,1.343 v1(22.409,1.64)
  Bottom Layer w0.3: U2.5 1.867,1.733 1.874,1.74 2.242,1.74 U2.4@2.842,2.34 ; U2.6 2.517,2.383 U2.4@2.842,2.708 ; U2.7 U2.7@1.792,3.033 ; v1(3.048,4.508) 2.991,4.451 2.778,4.451 2.758,4.43 2.323,4.43 2.147,4.254 2.147,3.388 U2.7@1.792,3.033 ; U2.4@4.287,1.733 3.817,1.733 3.81,1.74 3.442,1.74 U2.4@2.842,2.34 ; Debug.2 8.47,18.25 v1(15.178,18.25) ; v1(21.717,13.792) 22.381,14.457 v1(22.381,15.292) ; v1(26.369,13.611) 26.404,13.576 26.404,13.186 26.789,12.801 28.646,12.801 29.09,13.245 32.649,13.245 v1(33.571,14.167) ; U2.7@1.792,3.033 2.517,3.033 U2.4@2.842,2.708 ; U2.4@2.842,2.34 U2.4@2.842,2.708
  other v1: 23.368,4.466 22.336,7.172 8.632,13.431 19.31,15.167
WVDD: C5.2 C7.2 C8.1 C10.2 C11.2 D1.1 D2.1 D3.1 D4.1 Debug.1 L1.1 LS1.1A PW3.3V.6 PW3.3V.7 R10.1 R11.1 R12.1 U1.8 U1.13 U2.8 | length 101.8
  Top Layer w0.3: D1.1 1.044,10.819 v1(1.044,12.767) 3.777,12.767 4.826,13.816 4.826,16.18 5.696,17.05 6,17.05 Debug.1 6.35,18.3 7.354,19.304 11.822,19.304 12.776,18.35 13.138,18.35 13.32,18.168 13.32,18.396 13.918,18.994 21.718,18.994 22.318,18.394 22.494,18.394 ; LS1.1A 18.725,5.76 ; R11.1 R10.1 20.192,9.637 22.113,9.637 22.12,9.644 22.598,9.644 ; C10.2 20.449,1.645 19.818,1.645 v1(19.812,1.651) 19.03,2.433 v1(16.735,2.433) 17.235,2.933 17.235,3.9 C7.2 17.226,4.876 17.934,5.584 18.541,5.584 18.717,5.76 18.725,5.76 ; C8.1 23.368,9.114 C8.1@23.099,9.383 ; PW3.3V.7@25.094,7.077 24.754,7.077 24.511,7.32 24.511,8.243 ; PW3.3V.7 25.119,6.906 25.094,6.881 24.994,6.881 23.828,5.715 22.379,5.715 22.334,5.76 18.725,5.76 ; PW3.3V.6 25.119,9.609 25.094,9.584 24.545,9.584 24.257,9.296 24.257,9.287 24.511,9.033 24.511,8.243 ; C11.2 C11.2@32.893,15.702 ; v1(33.71,15.702) C11.2@32.893,15.702 ; 22.494,18.394 22.494,17.006 21.731,16.244 21.731,14.898 22.598,14.031 22.598,9.644 ; 22.494,18.394 23.498,18.394 23.879,18.013 23.879,17.474 23.869,17.464 23.869,17.421 24.553,16.737 31.858,16.737 C11.2@32.893,15.702 ; 22.598,9.644 22.838,9.644 C8.1@23.099,9.383 ; C8.1@23.099,9.383 23.371,9.383 23.572,9.182 24.511,8.243
  Bottom Layer w0.2: v1@19.685,1.768 U1.8 ; v1(24.257,9.359) 24.365,9.359 24.486,9.48 D2.1 27.635,9.48 29.72,7.395 31.397,7.395 32.442,6.35 D4.1@32.921,6.35
  Bottom Layer w0.3: v1(1.044,12.767) 1.044,7.836 2.144,6.736 R12.1 2.094,5.15 1.994,5.05 1.994,4.808 1.469,4.283 1.469,3.683 U2.8 ; v1(16.735,2.433) 16.735,3.358 16.76,3.383 U1.13 ; D3.1@32.764,15.386 33.164,15.386 33.48,15.702 v1(33.71,15.702)
XRES: Debug.3 M1.2 | length 19.6
  Top Layer w0.2: M1.2 5.79,4.1 6.767,4.1 7.204,4.537 7.204,6.733 9.398,8.927 9.398,9.906 5.405,13.899 5.405,15.717 5.983,16.295 7.88,16.295 8.89,17.305 Debug.3
pads on no net: Charge.1 D5. J1.2 J1.3 J1.4 M1.10 M1.13 M1.18 M1.19 M1.21 M1.24 M1.25 M1.28 U1.1 U1.2 U1.3 U1.4 U1.5 U1.6 U1.7 U1.14 U1.15 U1.16 U1.17 U1.19 U1.20 U1.21 U1.22 U1.25 U3.8 U3.9 U3.10 U3.12 U3.13 U3.14 U3.15 U3.16 U3.17 U3.18 U3.19 U3.20 U3.21 U3.22

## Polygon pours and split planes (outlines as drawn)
WGND on Bottom Layer "WGND_L02_P001" (solid, pour order 1): 0,-0.075 8.255,-0.075 ccw(c8.255,0) 8.328,-0.018 ccw(c8.31,0.055) 8.385,0.055 8.385,4.905 14.798,4.905 14.798,0.027 ccw(c14.873,0.027) 14.835,-0.038 ccw(c14.9,0) 14.9,-0.075 40,-0.075 ccw(c40,0) 40.075,0 40.075,20 ccw(c40,20) 40,20.075 0,20.075 ccw(c0,20) -0.075,20 -0.075,0 ccw(c0,0)
WGND on Top Layer "Top Layer-No Net" (solid, pour order 0): 0,-0.075 8.255,-0.075 ccw(c8.255,0) 8.328,-0.018 ccw(c8.31,0.055) 8.385,0.055 8.385,4.905 14.798,4.905 14.798,0.027 ccw(c14.873,0.027) 14.835,-0.038 ccw(c14.9,0) 14.9,-0.075 40,-0.075 ccw(c40,0) 40.075,0 40.075,20 ccw(c40,20) 40,20.075 0,20.075 ccw(c0,20) -0.075,20 -0.075,0 ccw(c0,0)

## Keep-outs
Keep-Out Layer:
  lines w0.15: 10.6,20 10.634,19.966 10.634,20 ; 0,0 8.255,0 8.31,0.055 8.31,4.98 14.873,4.98 14.873,0.027 14.9,0 40,0 40,20 0,20 0,0

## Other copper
Top Layer:
  rectangle net WGND: 26.119,7.006 26.619,7.985
  rectangle net WGND: 25.619,8.636 26.698,9.666
  pour cut-out: 19.05,0 19.03,0.02 19.03,6.119 19.016,6.133 5.207,6.133 5.207,0
Bottom Layer:
  pour cut-out: 19.05,0 19.03,0.02 19.03,6.119 19.016,6.133 5.207,6.133 5.207,0
  pour cut-out: 9.073,-1.905
  pour cut-out: 17.018,0

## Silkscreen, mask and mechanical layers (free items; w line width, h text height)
Mechanical 2:
  lines w0.5: 8.632,0.2 14.56,0.2 14.55,4.66 8.632,4.66 8.632,0.2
